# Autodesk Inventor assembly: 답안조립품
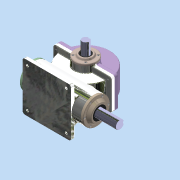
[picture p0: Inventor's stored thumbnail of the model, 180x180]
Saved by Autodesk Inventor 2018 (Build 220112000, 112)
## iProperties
Created: 2023-07
Part Number: 답안조립품
Material: 일반
Document SubType Name: Assembly
Designer: home
Author: home
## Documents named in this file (14)
- C:\Users\kimgi\Desktop\730706V1002\답안조립품.iam
- C:\Users\kimgi\Desktop\730706V1002\본체.ipt
- C:\Users\kimgi\Desktop\730706V1002\앞커버.ipt
- C:\Users\kimgi\Desktop\730706V1002\뒤커버.ipt
- C:\Users\kimgi\Desktop\730706V1002\깊은 홈 볼 베어링 6209.ipt
- C:\Users\kimgi\Desktop\730706V1002\웜 샤프트.ipt
- C:\Users\kimgi\Desktop\730706V1002\오일 실 35 55 11.ipt
- C:\Users\kimgi\Desktop\730706V1002\본체 커버.ipt
- C:\Users\kimgi\Desktop\730706V1002\서브커버.ipt
- C:\Users\kimgi\Desktop\730706V1002\오일 실 30 42 7.ipt
- C:\Users\kimgi\Desktop\730706V1002\깊은 홈 볼 베어링 6206.ipt
- C:\Users\kimgi\Desktop\730706V1002\웜 휠.ipt
- C:\Users\kimgi\Desktop\730706V1002\육각 소켓 머리 볼트 M5 x 12.ipt
- C:\Users\kimgi\Desktop\730706V1002\육각 소켓 머리 볼트 M6 x 20.ipt
